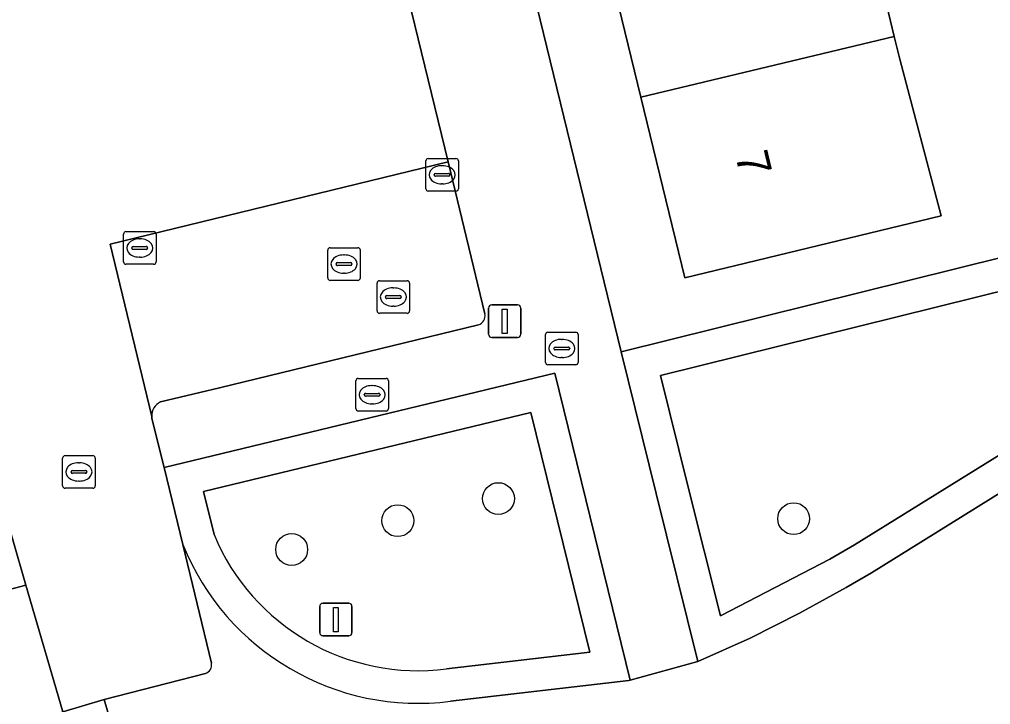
# Model space of a CAD drawing. Extents: x 159716 to 160783, y 383290 to 384031.
# Drawn here: x 160223.98 to 160253.79, y 383501.77 to 383522.79 of the extents above; entities that cross this region are included whole.
import ezdxf

# ---------------------------------------------------------------- set-up
doc = ezdxf.new("R2010")
doc.units = 0
for name, color, linetype in [('IMGEO_Boom', 7, 'Continuous'), ('IMGEO_Erf', 7, 'Continuous'), ('IMGEO_Grasland_overig', 7, 'Continuous'), ('IMGEO_Groenvoorziening', 7, 'Continuous'), ('IMGEO_Haag', 7, 'Continuous'), ('IMGEO_Kolk', 7, 'Continuous'), ('IMGEO_Lichtmast', 7, 'Continuous'), ('IMGEO_Pand', 7, 'Continuous'), ('IMGEO_Pand_nummerreeks', 7, 'Continuous'), ('IMGEO_Parkeervlak_open', 7, 'Continuous'), ('IMGEO_Rijbaan_lokaal_open', 7, 'Continuous'), ('IMGEO_Rioolput', 7, 'Continuous'), ('IMGEO_Voetpad_open', 7, 'Continuous')]:
    doc.layers.add(name, color=color, linetype=linetype)

msp = doc.modelspace()

# ---------------------------------------------------------------- linework, layer by layer
at = {"layer": 'IMGEO_Boom'}
for centre in [(160238.684, 383508.085), (160235.596, 383507.408), (160247.745, 383507.469), (160232.339, 383506.523)]:
    msp.add_circle(centre, 0.489, dxfattribs=at)
at = {"layer": 'IMGEO_Erf'}
for points in [[(160216.737, 383500), (160215.819, 383503.217), (160224.183, 383505.425), (160223.375, 383508.213), (160214.818, 383505.771), (160212.184, 383505.019), (160211.76, 383506.503), (160207.828, 383505.379), (160206.604, 383509.664), (160210.537, 383510.788), (160213.102, 383511.521), (160221.749, 383513.824), (160221.586, 383514.545), (160221.02, 383516.821), (160214.5, 383539.845), (160209.46, 383556.921), (160208.467, 383560.285), (160208.331, 383560.287), (160207.569, 383560.131), (160206.481, 383559.908)], [(160255.541, 383556.399), (160249.88, 383555.027), (160244.377, 383553.693), (160238.875, 383552.361), (160233.373, 383551.027), (160234.348, 383547.003), (160231.853, 383546.399), (160231.626, 383547.337), (160228.619, 383546.609), (160227.871, 383549.693), (160227.072, 383549.499), (160222.173, 383548.452), (160223.853, 383541.771), (160224.121, 383540.671), (160229.666, 383542.021), (160230.628, 383537.987), (160228.936, 383537.573), (160225.103, 383536.646), (160225.36, 383535.533), (160236.232, 383538.092), (160242.449, 383512.59), (160267.426, 383518.786)], [(160228.875, 383494.06), (160226.581, 383501.916), (160225.318, 383501.545)]]:
    msp.add_lwpolyline(points, dxfattribs=at)
msp.add_lwpolyline([(160252.089, 383534.175), (160253.371, 383528.845), (160249.476, 383527.908), (160250.833, 383522.268), (160251.002, 383521.564), (160252.269, 383516.763), (160244.402, 383514.857), (160243.056, 383520.398), (160241.686, 383526.035), (160240.391, 383531.362), (160239.188, 383536.311), (160238.978, 383537.176), (160239.27, 383537.247), (160238.915, 383538.705), (160245.816, 383540.381), (160246.193, 383538.813), (160246.817, 383538.963), (160248.194, 383533.238)], close=True, dxfattribs=at)
at = {"layer": 'IMGEO_Grasland_overig'}
for points in [[(160237.096, 383502.861), (160241.489, 383503.369), (160239.682, 383510.731), (160229.637, 383508.3)], [(160229.637, 383508.3), (160229.957, 383506.981)]]:
    msp.add_lwpolyline(points, dxfattribs=at)
msp.add_arc((160236.219, 383509.587), 6.783, 202.5944, 277.4261, dxfattribs=at)
at = {"layer": 'IMGEO_Groenvoorziening'}
for points in [[(160267.896, 383516.836), (160267.426, 383518.786), (160242.449, 383512.59), (160243.522, 383508.24), (160244.809, 383503.084), (160246.408, 383503.805), (160247.924, 383504.568), (160249.354, 383505.355), (160250.132, 383505.812), (160255.384, 383509.071)], [(160245.504, 383504.484), (160248.856, 383506.222), (160249.611, 383506.665), (160254.857, 383509.921), (160266.754, 383517.304), (160266.69, 383517.573), (160243.659, 383511.86), (160244.493, 383508.481)], [(160245.504, 383504.484), (160244.493, 383508.481), (160243.659, 383511.86), (160266.69, 383517.573), (160266.754, 383517.304), (160254.857, 383509.921), (160249.611, 383506.665), (160248.856, 383506.222)]]:
    msp.add_lwpolyline(points, close=True, dxfattribs=at)
for points in [[(160237.218, 383501.868), (160242.684, 383502.5), (160242.729, 383502.512), (160240.416, 383511.937), (160228.43, 383509.037)], [(160229.957, 383506.981), (160229.637, 383508.3), (160239.682, 383510.731), (160241.489, 383503.369)], [(160228.43, 383509.037), (160229.003, 383506.672)], [(160241.489, 383503.369), (160237.096, 383502.861)]]:
    msp.add_lwpolyline(points, dxfattribs=at)
for centre, radius, start, end in [((160236.219, 383509.587), 6.783, 202.5944, 277.4261), ((160236.22, 383509.587), 7.783, 201.9933, 277.3698)]:
    msp.add_arc(centre, radius, start, end, dxfattribs=at)
at = {"layer": 'IMGEO_Haag'}
for points in [[(160250.132, 383505.812), (160255.384, 383509.071), (160267.896, 383516.836), (160267.426, 383518.786), (160242.449, 383512.59), (160243.522, 383508.24), (160244.809, 383503.084), (160246.408, 383503.805), (160247.924, 383504.568), (160249.354, 383505.355)], [(160245.504, 383504.484), (160244.493, 383508.481), (160243.659, 383511.86), (160266.69, 383517.573), (160266.754, 383517.304), (160254.857, 383509.921), (160249.611, 383506.665), (160248.856, 383506.222)]]:
    msp.add_lwpolyline(points, close=True, dxfattribs=at)
for points in [[(160237.218, 383501.868), (160242.684, 383502.5), (160242.729, 383502.512), (160240.416, 383511.937), (160228.43, 383509.037)], [(160229.957, 383506.981), (160229.637, 383508.3), (160239.682, 383510.731), (160241.489, 383503.369)], [(160228.43, 383509.037), (160229.003, 383506.672)], [(160241.489, 383503.369), (160237.096, 383502.861)]]:
    msp.add_lwpolyline(points, dxfattribs=at)
for centre, radius, start, end in [((160236.219, 383509.587), 6.783, 202.5944, 277.4261), ((160236.22, 383509.587), 7.783, 201.9933, 277.3698)]:
    msp.add_arc(centre, radius, start, end, dxfattribs=at)
at = {"layer": 'IMGEO_Kolk'}
for p, q in [((160236.455, 383517.595), (160236.455, 383518.447)), ((160236.53, 383518.521), (160237.382, 383518.521)), ((160236.943, 383518.301), (160236.968, 383518.301)), ((160237.456, 383518.447), (160237.456, 383517.595)), ((160236.714, 383518.015), (160236.714, 383518.027)), ((160236.757, 383518.064), (160237.155, 383518.064)), ((160237.198, 383518.027), (160237.198, 383518.015)), ((160237.152, 383517.978), (160236.754, 383517.978)), ((160236.966, 383517.741), (160236.941, 383517.741)), ((160237.382, 383517.521), (160236.53, 383517.521)), ((160227.176, 383515.35), (160227.176, 383516.202)), ((160227.251, 383516.276), (160228.103, 383516.276)), ((160228.177, 383516.202), (160228.177, 383515.35)), ((160227.664, 383516.056), (160227.689, 383516.056)), ((160227.435, 383515.77), (160227.435, 383515.782)), ((160227.873, 383515.733), (160227.475, 383515.733)), ((160227.478, 383515.819), (160227.876, 383515.819)), ((160227.919, 383515.782), (160227.919, 383515.77)), ((160227.687, 383515.496), (160227.662, 383515.496)), ((160228.103, 383515.276), (160227.251, 383515.276)), ((160225.385, 383509.404), (160226.237, 383509.404)), ((160225.31, 383508.478), (160225.31, 383509.33)), ((160225.798, 383509.184), (160225.823, 383509.184)), ((160226.311, 383509.33), (160226.311, 383508.478)), ((160225.569, 383508.898), (160225.569, 383508.91)), ((160226.007, 383508.861), (160225.609, 383508.861)), ((160225.612, 383508.947), (160226.01, 383508.947)), ((160226.053, 383508.91), (160226.053, 383508.898)), ((160225.821, 383508.624), (160225.796, 383508.624)), ((160226.237, 383508.404), (160225.385, 383508.404))]:
    msp.add_line(p, q, dxfattribs=at)
for points in [[(160236.455, 383517.595), (160236.455, 383518.447)], [(160236.53, 383518.521), (160237.382, 383518.521)], [(160237.456, 383518.447), (160237.456, 383517.595)], [(160237.382, 383517.521), (160236.53, 383517.521)], [(160227.176, 383515.35), (160227.176, 383516.202)], [(160227.251, 383516.276), (160228.103, 383516.276)], [(160228.177, 383516.202), (160228.177, 383515.35)], [(160228.103, 383515.276), (160227.251, 383515.276)], [(160225.385, 383509.404), (160226.237, 383509.404)], [(160225.31, 383508.478), (160225.31, 383509.33)], [(160226.311, 383509.33), (160226.311, 383508.478)], [(160226.237, 383508.404), (160225.385, 383508.404)]]:
    msp.add_lwpolyline(points, dxfattribs=at)
for centre, radius, start, end in [((160236.532, 383518.445), 0.0765, 91.552, 178.448), ((160236.532, 383518.445), 0.0765, 91.552, 178.448), ((160237.38, 383518.445), 0.0765, 1.552, 88.448), ((160237.38, 383518.445), 0.0765, 1.552, 88.448), ((160236.754, 383518.024), 0.0403, 85.8775, 175.7526), ((160236.751, 383518.014), 0.0366, 178.938, 274.7102), ((160237.155, 383518.021), 0.043, 264.8664, 352.4533), ((160237.159, 383518.026), 0.0386, 1.7309, 96.639), ((160236.532, 383517.597), 0.0765, 181.552, 268.448), ((160236.532, 383517.597), 0.0765, 181.552, 268.448), ((160237.38, 383517.597), 0.0765, 271.552, 358.448), ((160237.38, 383517.597), 0.0765, 271.552, 358.448), ((160227.253, 383516.2), 0.0765, 91.552, 178.448), ((160227.253, 383516.2), 0.0765, 91.552, 178.448), ((160228.101, 383516.2), 0.0765, 1.552, 88.448), ((160228.101, 383516.2), 0.0765, 1.552, 88.448), ((160227.475, 383515.779), 0.0403, 85.8775, 175.7526), ((160227.472, 383515.769), 0.0366, 178.938, 274.7102), ((160227.876, 383515.776), 0.043, 264.8664, 352.4533), ((160227.88, 383515.781), 0.0386, 1.7309, 96.639), ((160227.253, 383515.352), 0.0765, 181.552, 268.448), ((160227.253, 383515.352), 0.0765, 181.552, 268.448), ((160228.101, 383515.352), 0.0765, 271.552, 358.448), ((160228.101, 383515.352), 0.0765, 271.552, 358.448), ((160225.387, 383509.328), 0.0765, 91.552, 178.448), ((160225.387, 383509.328), 0.0765, 91.552, 178.448), ((160226.235, 383509.328), 0.0765, 1.552, 88.448), ((160226.235, 383509.328), 0.0765, 1.552, 88.448), ((160225.609, 383508.907), 0.0403, 85.8775, 175.7526), ((160225.606, 383508.897), 0.0366, 178.938, 274.7102), ((160226.01, 383508.904), 0.043, 264.8664, 352.4533), ((160226.014, 383508.909), 0.0386, 1.7309, 96.639), ((160225.387, 383508.48), 0.0765, 181.552, 268.448), ((160225.387, 383508.48), 0.0765, 181.552, 268.448), ((160226.235, 383508.48), 0.0765, 271.552, 358.448), ((160226.235, 383508.48), 0.0765, 271.552, 358.448)]:
    msp.add_arc(centre, radius, start, end, dxfattribs=at)
for centre, major_axis, ratio, start_param, end_param in [((160236.942, 383518.021), (-0.387, 0.002), 0.722429, 4.712389, 7.853982), ((160236.967, 383518.021), (-0.39, 0.002), 0.717154, 1.570796, 4.712389), ((160227.663, 383515.776), (-0.387, 0.002), 0.722429, 4.712389, 7.853982), ((160227.688, 383515.776), (-0.39, 0.002), 0.717154, 1.570796, 4.712389), ((160225.797, 383508.904), (-0.387, 0.002), 0.722429, 4.712389, 7.853982), ((160225.822, 383508.904), (-0.39, 0.002), 0.717154, 1.570796, 4.712389)]:
    msp.add_ellipse(centre, major_axis=major_axis, ratio=ratio, start_param=start_param, end_param=end_param, dxfattribs=at)
at = {"layer": 'IMGEO_Lichtmast'}
for p, q in [((160238.382, 383513.126), (160238.382, 383513.926)), ((160238.382, 383513.926), (160238.382, 383513.126)), ((160238.482, 383514.026), (160239.272, 383514.026)), ((160239.272, 383514.026), (160238.482, 383514.026)), ((160239.372, 383513.926), (160239.372, 383513.126)), ((160239.372, 383513.126), (160239.372, 383513.926)), ((160239.272, 383513.026), (160238.482, 383513.026)), ((160238.482, 383513.026), (160239.272, 383513.026)), ((160233.2, 383503.972), (160233.2, 383504.772)), ((160233.2, 383504.772), (160233.2, 383503.972)), ((160233.3, 383504.872), (160234.09, 383504.872)), ((160234.09, 383504.872), (160233.3, 383504.872)), ((160234.19, 383504.772), (160234.19, 383503.972)), ((160234.19, 383503.972), (160234.19, 383504.772)), ((160234.09, 383503.872), (160233.3, 383503.872)), ((160233.3, 383503.872), (160234.09, 383503.872))]:
    msp.add_line(p, q, dxfattribs=at)
for points in [[(160238.802, 383513.901), (160238.952, 383513.901), (160238.952, 383513.151), (160238.802, 383513.151), (160238.802, 383513.901)], [(160233.62, 383504.747), (160233.77, 383504.747), (160233.77, 383503.997), (160233.62, 383503.997), (160233.62, 383504.747)]]:
    msp.add_lwpolyline(points, dxfattribs=at)
for centre, start, end in [((160238.482, 383513.926), 90, 180), ((160238.482, 383513.926), 90, 180), ((160239.272, 383513.926), 0, 90), ((160239.272, 383513.926), 360, 90), ((160238.482, 383513.126), 180, 270), ((160238.482, 383513.126), 180, 270), ((160239.272, 383513.126), 270, 0), ((160239.272, 383513.126), 270, 0), ((160233.3, 383504.772), 90, 180), ((160233.3, 383504.772), 90, 180), ((160234.09, 383504.772), 0, 90), ((160234.09, 383504.772), 360, 90), ((160233.3, 383503.972), 180, 270), ((160233.3, 383503.972), 180, 270), ((160234.09, 383503.972), 270, 0), ((160234.09, 383503.972), 270, 0)]:
    msp.add_arc(centre, 0.1, start, end, dxfattribs=at)
at = {"layer": 'IMGEO_Pand'}
for points in [[(160249.476, 383527.908), (160241.686, 383526.035), (160243.056, 383520.398), (160250.833, 383522.268)], [(160251.002, 383521.564), (160250.833, 383522.268), (160243.056, 383520.398), (160244.402, 383514.857), (160252.269, 383516.763)], [(160224.183, 383505.425), (160215.819, 383503.217), (160216.737, 383500), (160216.995, 383499.098), (160225.318, 383501.545)]]:
    msp.add_lwpolyline(points, close=True, dxfattribs=at)
at = {"layer": 'IMGEO_Parkeervlak_open'}
for points in [[(160237.139, 383518.423), (160226.769, 383515.897), (160228.045, 383510.608)], [(160238.269, 383513.755), (160237.139, 383518.423)], [(160228.312, 383511.052), (160230.128, 383511.485), (160238.07, 383513.422)]]:
    msp.add_lwpolyline(points, dxfattribs=at)
for centre, radius, start, end in [((160237.997, 383513.691), 0.279, 285.0702, 13.2049), ((160228.524, 383510.622), 0.48, 116.2859, 181.6728)]:
    msp.add_arc(centre, radius, start, end, dxfattribs=at)
at = {"layer": 'IMGEO_Rijbaan_lokaal_open'}
for points in [[(160221.303, 383538.588), (160216.391, 383558.613), (160211.542, 383557.498), (160221.949, 383514.678), (160221.586, 383514.545), (160221.749, 383513.824), (160223.375, 383508.213), (160224.183, 383505.425), (160225.318, 383501.545), (160226.581, 383501.916), (160229.691, 383502.716)], [(160229.879, 383503.039), (160229.003, 383506.672), (160228.43, 383509.037), (160228.052, 383510.546), (160228.045, 383510.608), (160226.769, 383515.897), (160237.139, 383518.423), (160234.497, 383529.288), (160226.865, 383527.441), (160224.539, 383526.869)], [(160258.634, 383501.395), (160259.897, 383502.144), (160257.606, 383505.656), (160255.384, 383509.071), (160250.132, 383505.812), (160249.354, 383505.355), (160247.924, 383504.568), (160246.408, 383503.805), (160244.809, 383503.084), (160242.729, 383502.512), (160242.684, 383502.5), (160237.218, 383501.868)], [(160229.003, 383506.672), (160229.879, 383503.039)], [(160229.691, 383502.716), (160226.581, 383501.916), (160228.875, 383494.06), (160231.728, 383484.404), (160235.251, 383485.468), (160233.661, 383487.923)]]:
    msp.add_lwpolyline(points, dxfattribs=at)
for centre, radius, start, end in [((160236.22, 383509.587), 7.783, 201.9933, 277.3698), ((160229.594, 383502.989), 0.289, 289.5461, 10.0514), ((160229.594, 383502.989), 0.289, 289.5461, 10.0514)]:
    msp.add_arc(centre, radius, start, end, dxfattribs=at)
at = {"layer": 'IMGEO_Rioolput'}
for p, q in [((160233.445, 383514.856), (160233.445, 383515.708)), ((160233.52, 383515.782), (160234.372, 383515.782)), ((160234.446, 383515.708), (160234.446, 383514.856)), ((160233.747, 383515.325), (160234.145, 383515.325)), ((160233.933, 383515.562), (160233.958, 383515.562)), ((160233.704, 383515.276), (160233.704, 383515.288)), ((160234.142, 383515.239), (160233.744, 383515.239)), ((160234.188, 383515.288), (160234.188, 383515.276)), ((160234.372, 383514.782), (160233.52, 383514.782)), ((160233.956, 383515.002), (160233.931, 383515.002)), ((160235.034, 383514.77), (160235.886, 383514.77)), ((160234.959, 383513.844), (160234.959, 383514.696)), ((160235.447, 383514.55), (160235.472, 383514.55)), ((160235.96, 383514.696), (160235.96, 383513.844)), ((160235.218, 383514.264), (160235.218, 383514.276)), ((160235.656, 383514.227), (160235.258, 383514.227)), ((160235.261, 383514.313), (160235.659, 383514.313)), ((160235.702, 383514.276), (160235.702, 383514.264)), ((160235.47, 383513.99), (160235.445, 383513.99)), ((160235.886, 383513.77), (160235.034, 383513.77)), ((160240.129, 383512.266), (160240.129, 383513.118)), ((160240.204, 383513.192), (160241.056, 383513.192)), ((160240.617, 383512.972), (160240.642, 383512.972)), ((160241.13, 383513.118), (160241.13, 383512.266)), ((160240.388, 383512.686), (160240.388, 383512.698)), ((160240.826, 383512.649), (160240.428, 383512.649)), ((160240.431, 383512.735), (160240.829, 383512.735)), ((160240.872, 383512.698), (160240.872, 383512.686)), ((160240.64, 383512.412), (160240.615, 383512.412)), ((160241.056, 383512.192), (160240.204, 383512.192)), ((160234.384, 383511.772), (160235.236, 383511.772)), ((160234.309, 383510.846), (160234.309, 383511.698)), ((160234.797, 383511.552), (160234.822, 383511.552)), ((160235.31, 383511.698), (160235.31, 383510.846)), ((160234.568, 383511.266), (160234.568, 383511.278)), ((160235.006, 383511.229), (160234.608, 383511.229)), ((160234.611, 383511.315), (160235.009, 383511.315)), ((160235.052, 383511.278), (160235.052, 383511.266)), ((160234.82, 383510.992), (160234.795, 383510.992)), ((160235.236, 383510.772), (160234.384, 383510.772))]:
    msp.add_line(p, q, dxfattribs=at)
for points in [[(160233.445, 383514.856), (160233.445, 383515.708)], [(160233.52, 383515.782), (160234.372, 383515.782)], [(160234.446, 383515.708), (160234.446, 383514.856)], [(160234.372, 383514.782), (160233.52, 383514.782)], [(160235.034, 383514.77), (160235.886, 383514.77)], [(160234.959, 383513.844), (160234.959, 383514.696)], [(160235.96, 383514.696), (160235.96, 383513.844)], [(160235.886, 383513.77), (160235.034, 383513.77)], [(160240.129, 383512.266), (160240.129, 383513.118)], [(160240.204, 383513.192), (160241.056, 383513.192)], [(160241.13, 383513.118), (160241.13, 383512.266)], [(160241.056, 383512.192), (160240.204, 383512.192)], [(160234.384, 383511.772), (160235.236, 383511.772)], [(160234.309, 383510.846), (160234.309, 383511.698)], [(160235.31, 383511.698), (160235.31, 383510.846)], [(160235.236, 383510.772), (160234.384, 383510.772)]]:
    msp.add_lwpolyline(points, dxfattribs=at)
for centre, radius, start, end in [((160233.522, 383515.706), 0.0765, 91.552, 178.448), ((160233.522, 383515.706), 0.0765, 91.552, 178.448), ((160234.37, 383515.706), 0.0765, 1.552, 88.448), ((160234.37, 383515.706), 0.0765, 1.552, 88.448), ((160233.744, 383515.285), 0.0403, 85.8775, 175.7526), ((160234.149, 383515.287), 0.0386, 1.7309, 96.639), ((160233.741, 383515.275), 0.0366, 178.938, 274.7102), ((160234.145, 383515.282), 0.043, 264.8664, 352.4533), ((160233.522, 383514.858), 0.0765, 181.552, 268.448), ((160233.522, 383514.858), 0.0765, 181.552, 268.448), ((160234.37, 383514.858), 0.0765, 271.552, 358.448), ((160234.37, 383514.858), 0.0765, 271.552, 358.448), ((160235.036, 383514.694), 0.0765, 91.552, 178.448), ((160235.036, 383514.694), 0.0765, 91.552, 178.448), ((160235.884, 383514.694), 0.0765, 1.552, 88.448), ((160235.884, 383514.694), 0.0765, 1.552, 88.448), ((160235.258, 383514.273), 0.0403, 85.8775, 175.7526), ((160235.255, 383514.263), 0.0366, 178.938, 274.7102), ((160235.659, 383514.27), 0.043, 264.8664, 352.4533), ((160235.663, 383514.275), 0.0386, 1.7309, 96.639), ((160235.036, 383513.846), 0.0765, 181.552, 268.448), ((160235.036, 383513.846), 0.0765, 181.552, 268.448), ((160235.884, 383513.846), 0.0765, 271.552, 358.448), ((160235.884, 383513.846), 0.0765, 271.552, 358.448), ((160240.206, 383513.116), 0.0765, 91.552, 178.448), ((160240.206, 383513.116), 0.0765, 91.552, 178.448), ((160241.054, 383513.116), 0.0765, 1.552, 88.448), ((160241.054, 383513.116), 0.0765, 1.552, 88.448), ((160240.428, 383512.695), 0.0403, 85.8775, 175.7526), ((160240.425, 383512.685), 0.0366, 178.938, 274.7102), ((160240.829, 383512.692), 0.043, 264.8664, 352.4533), ((160240.833, 383512.697), 0.0386, 1.7309, 96.639), ((160240.206, 383512.268), 0.0765, 181.552, 268.448), ((160240.206, 383512.268), 0.0765, 181.552, 268.448), ((160241.054, 383512.268), 0.0765, 271.552, 358.448), ((160241.054, 383512.268), 0.0765, 271.552, 358.448), ((160234.386, 383511.696), 0.0765, 91.552, 178.448), ((160234.386, 383511.696), 0.0765, 91.552, 178.448), ((160235.234, 383511.696), 0.0765, 1.552, 88.448), ((160235.234, 383511.696), 0.0765, 1.552, 88.448), ((160234.608, 383511.275), 0.0403, 85.8775, 175.7526), ((160234.605, 383511.265), 0.0366, 178.938, 274.7102), ((160235.009, 383511.272), 0.043, 264.8664, 352.4533), ((160235.013, 383511.277), 0.0386, 1.7309, 96.639), ((160234.386, 383510.848), 0.0765, 181.552, 268.448), ((160234.386, 383510.848), 0.0765, 181.552, 268.448), ((160235.234, 383510.848), 0.0765, 271.552, 358.448), ((160235.234, 383510.848), 0.0765, 271.552, 358.448)]:
    msp.add_arc(centre, radius, start, end, dxfattribs=at)
for centre, major_axis, ratio, start_param, end_param in [((160233.932, 383515.282), (-0.387, 0.002), 0.722429, 4.712389, 7.853982), ((160233.957, 383515.282), (-0.39, 0.002), 0.717154, 1.570796, 4.712389), ((160235.446, 383514.27), (-0.387, 0.002), 0.722429, 4.712389, 7.853982), ((160235.471, 383514.27), (-0.39, 0.002), 0.717154, 1.570796, 4.712389), ((160240.616, 383512.692), (-0.387, 0.002), 0.722429, 4.712389, 7.853982), ((160240.641, 383512.692), (-0.39, 0.002), 0.717154, 1.570796, 4.712389), ((160234.796, 383511.272), (-0.387, 0.002), 0.722429, 4.712389, 7.853982), ((160234.821, 383511.272), (-0.39, 0.002), 0.717154, 1.570796, 4.712389)]:
    msp.add_ellipse(centre, major_axis=major_axis, ratio=ratio, start_param=start_param, end_param=end_param, dxfattribs=at)
at = {"layer": 'IMGEO_Voetpad_open'}
for points in [[(160228.045, 383510.608), (160228.052, 383510.546), (160228.43, 383509.037), (160240.416, 383511.937), (160242.729, 383502.512), (160244.809, 383503.084), (160243.522, 383508.24), (160242.449, 383512.59), (160236.232, 383538.092), (160225.36, 383535.533), (160225.103, 383536.646), (160224.443, 383539.378), (160224.121, 383540.671), (160223.853, 383541.771), (160222.173, 383548.452), (160220.268, 383556.319)], [(160233.4, 383533.854), (160234.497, 383529.288), (160237.139, 383518.423), (160238.269, 383513.755)], [(160238.07, 383513.422), (160230.128, 383511.485), (160228.312, 383511.052)]]:
    msp.add_lwpolyline(points, dxfattribs=at)
for centre, radius, start, end in [((160237.997, 383513.691), 0.279, 285.0702, 13.2049), ((160228.524, 383510.622), 0.48, 116.2859, 181.6728)]:
    msp.add_arc(centre, radius, start, end, dxfattribs=at)

# ---------------------------------------------------------------- texts
at = {"layer": 'IMGEO_Pand_nummerreeks'}
msp.add_text('7', height=1, rotation=283.5273, dxfattribs=at).set_placement((160245.947, 383518.625))

doc.saveas('drawing.dxf')
